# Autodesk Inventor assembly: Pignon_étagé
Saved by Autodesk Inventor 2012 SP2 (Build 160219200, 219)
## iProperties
Created: 2013-08
Part Number: Pignon_étagé
Document SubType Name: Assembly
Designer: hilarion
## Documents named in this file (2)
- L:\STI2D\Ressources eleves\ITEC\Tsti2d Fichot 2013-14\Webcam motorisee\Pignon_étagé.iam
- L:\STI2D\Ressources eleves\ITEC\Tsti2d Fichot 2013-14\Webcam motorisee\Roue dentée Intermédiaire 2.ipt
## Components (1 placed, 1 different names)
1. Roue dentée Intermédiaire 2:1
